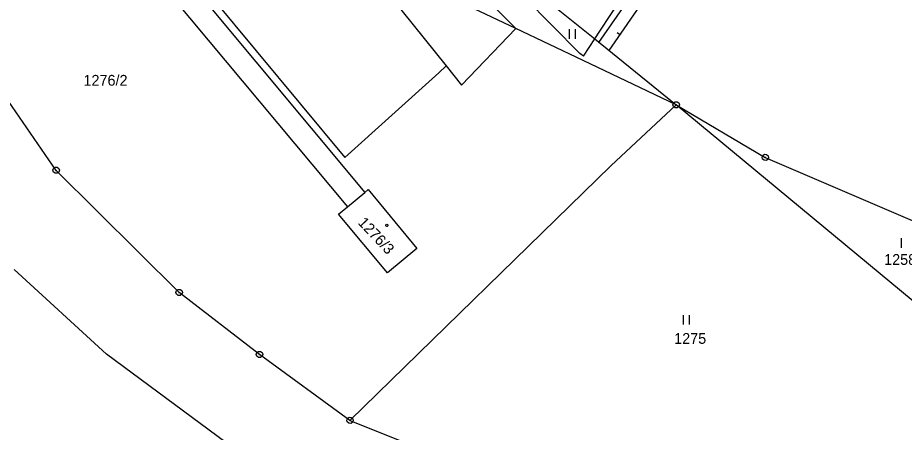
# Model space of a CAD drawing. Extents: x -806774 to -803680, y -1151731 to -1150053.
# Drawn here: x -804117.6 to -803977.7, y -1150702.1 to -1150636.6 of the extents above; entities that cross this region are included whole.
import ezdxf

# ---------------------------------------------------------------- set-up
doc = ezdxf.new("R2010")
doc.units = 0
for name, color, linetype in [('1', 7, 'Continuous'), ('12', 7, 'Continuous'), ('13', 7, 'Continuous'), ('2', 7, 'Continuous'), ('3', 7, 'Continuous'), ('5', 7, 'Continuous'), ('6', 7, 'Continuous'), ('8', 7, 'Continuous')]:
    doc.layers.add(name, color=color, linetype=linetype)

msp = doc.modelspace()

# ---------------------------------------------------------------- linework, layer by layer
at = {"layer": '1'}
for p, q in [((-804152.05, -1150554.87), (-804065.98, -1150658.69)), ((-804146.64, -1150563.54), (-804062.82, -1150664.2)), ((-804149.4, -1150565.85), (-804065.57, -1150666.5)), ((-804064.75, -1150612.44), (-804038.96, -1150638.33)), ((-804071.82, -1150616.91), (-804049.99, -1150644.23)), ((-804025.71, -1150638.73), (-804012.48, -1150618.32)), ((-804028.9, -1150642.28), (-804043.39, -1150627.53)), ((-804042.74, -1150626.9), (-804026.54, -1150639.97)), ((-804038.96, -1150638.33), (-804050.17, -1150633)), ((-804047.57, -1150647.28), (-804038.96, -1150638.33)), ((-804028.35, -1150643.39), (-804038.96, -1150638.33)), ((-804026.54, -1150639.97), (-804025.71, -1150638.73)), ((-804028.32, -1150642.67), (-804026.54, -1150639.97)), ((-804026.54, -1150639.97), (-804013.68, -1150650.38)), ((-804111.51, -1150660.72), (-804123.96, -1150642.72)), ((-804028.32, -1150642.67), (-804028.9, -1150642.28)), ((-804013.68, -1150650.38), (-804028.35, -1150643.39)), ((-804051.16, -1150645.3), (-804049.99, -1150644.23)), ((-804049.99, -1150644.23), (-804047.57, -1150647.28)), ((-804065.98, -1150658.69), (-804051.16, -1150645.3)), ((-804013.68, -1150650.38), (-804024.02, -1150660)), ((-804013.68, -1150650.38), (-803999.62, -1150658.69)), ((-803968.03, -1150688.27), (-804013.68, -1150650.38)), ((-803999.62, -1150658.69), (-803974.99, -1150669.28)), ((-804024.02, -1150660), (-804065.16, -1150700.21)), ((-804092.1, -1150680), (-804111.51, -1150660.72)), ((-804065.57, -1150666.5), (-804062.82, -1150664.2)), ((-804062.82, -1150664.2), (-804062.31, -1150663.77)), ((-804062.31, -1150663.77), (-804054.58, -1150673.04)), ((-804066.95, -1150667.66), (-804065.57, -1150666.5)), ((-804059.21, -1150676.92), (-804066.95, -1150667.66)), ((-804054.58, -1150673.04), (-804059.21, -1150676.92)), ((-804079.43, -1150689.81), (-804092.1, -1150680)), ((-804065.16, -1150700.21), (-804079.43, -1150689.81)), ((-804065.16, -1150700.21), (-804041.05, -1150709.83))]:
    msp.add_line(p, q, dxfattribs=at)
at = {"layer": '12'}
for p, q in [((-804065.57, -1150666.5), (-804062.82, -1150664.2)), ((-804062.82, -1150664.2), (-804062.31, -1150663.77)), ((-804062.31, -1150663.77), (-804054.58, -1150673.04)), ((-804066.95, -1150667.66), (-804065.57, -1150666.5)), ((-804059.21, -1150676.92), (-804066.95, -1150667.66)), ((-804054.58, -1150673.04), (-804059.21, -1150676.92))]:
    msp.add_line(p, q, dxfattribs=at)
at = {"layer": '13'}
for p, q in [((-804025.87, -1150640.52), (-804002.87, -1150607.2)), ((-804001.29, -1150608.42), (-804024.33, -1150641.77)), ((-804022.61, -1150639.27), (-804023.02, -1150638.99)), ((-804024.33, -1150641.77), (-804025.87, -1150640.52))]:
    msp.add_line(p, q, dxfattribs=at)
at = {"layer": '3'}
for p, q in [((-804030.59, -1150638.43), (-804030.59, -1150639.93)), ((-804029.59, -1150639.93), (-804029.59, -1150638.43)), ((-803978.16, -1150671.45), (-803978.16, -1150672.95)), ((-804012.57, -1150683.57), (-804012.57, -1150685.07)), ((-804011.57, -1150685.07), (-804011.57, -1150683.57))]:
    msp.add_line(p, q, dxfattribs=at)
at = {"layer": '5'}
msp.add_lwpolyline([(-804059.35, -1150669.24), (-804059.25, -1150669.26), (-804059.2, -1150669.35), (-804059.18, -1150669.41), (-804059.2, -1150669.5), (-804059.28, -1150669.57), (-804059.35, -1150669.58), (-804059.44, -1150669.55), (-804059.5, -1150669.49), (-804059.52, -1150669.41), (-804059.5, -1150669.32), (-804059.42, -1150669.25)], close=True, dxfattribs=at)
at = {"layer": '6'}
for p, q in [((-804103.55, -1150689.77), (-804118.13, -1150676.38)), ((-804084.74, -1150703.71), (-804103.55, -1150689.77))]:
    msp.add_line(p, q, dxfattribs=at)
at = {"layer": '8'}
for p, q in [((-804013.8, -1150650.38), (-804013.56, -1150650.38)), ((-803999.65, -1150658.57), (-803999.59, -1150658.81)), ((-804111.63, -1150660.72), (-804111.39, -1150660.72)), ((-804092.22, -1150680), (-804091.98, -1150680)), ((-804079.55, -1150689.81), (-804079.31, -1150689.81)), ((-804065.19, -1150700.09), (-804065.13, -1150700.33))]:
    msp.add_line(p, q, dxfattribs=at)
for points in [[(-804013.53, -1150649.9), (-804013.28, -1150650.08), (-804013.18, -1150650.37), (-804013.28, -1150650.66), (-804013.53, -1150650.84), (-804013.84, -1150650.84), (-804014.09, -1150650.66), (-804014.19, -1150650.37), (-804014.09, -1150650.08), (-804013.84, -1150649.9)], [(-803999.12, -1150658.73), (-803999.24, -1150659.02), (-803999.5, -1150659.18), (-803999.81, -1150659.14), (-804000.04, -1150658.94), (-804000.1, -1150658.63), (-803999.98, -1150658.35), (-803999.72, -1150658.19), (-803999.42, -1150658.22), (-803999.19, -1150658.43)], [(-804111.36, -1150660.24), (-804111.11, -1150660.42), (-804111.01, -1150660.71), (-804111.11, -1150661), (-804111.36, -1150661.18), (-804111.67, -1150661.18), (-804111.92, -1150661), (-804112.02, -1150660.71), (-804111.92, -1150660.42), (-804111.67, -1150660.24)], [(-804091.95, -1150679.52), (-804091.7, -1150679.7), (-804091.6, -1150679.99), (-804091.7, -1150680.28), (-804091.95, -1150680.46), (-804092.26, -1150680.46), (-804092.51, -1150680.28), (-804092.61, -1150679.99), (-804092.51, -1150679.7), (-804092.26, -1150679.52)], [(-804079.28, -1150689.33), (-804079.03, -1150689.51), (-804078.93, -1150689.8), (-804079.03, -1150690.09), (-804079.28, -1150690.27), (-804079.59, -1150690.27), (-804079.84, -1150690.09), (-804079.94, -1150689.8), (-804079.84, -1150689.51), (-804079.59, -1150689.33)], [(-804064.66, -1150700.25), (-804064.78, -1150700.54), (-804065.04, -1150700.7), (-804065.35, -1150700.66), (-804065.58, -1150700.46), (-804065.64, -1150700.15), (-804065.52, -1150699.87), (-804065.26, -1150699.71), (-804064.96, -1150699.74), (-804064.73, -1150699.95)]]:
    msp.add_lwpolyline(points, close=True, dxfattribs=at)

# ---------------------------------------------------------------- texts
at = {"layer": '2'}
for s, p in [('1276/2', (-804107.21, -1150647.35)), ('1258/5', (-803980.87, -1150675.65)), ('1275', (-804014, -1150688.12))]:
    msp.add_text(s, height=1.7, dxfattribs=at).set_placement(p)
msp.add_text('1276/3', height=1.7, rotation=313.1787, dxfattribs=at).set_placement((-804064, -1150669.07))

doc.saveas('drawing.dxf')
